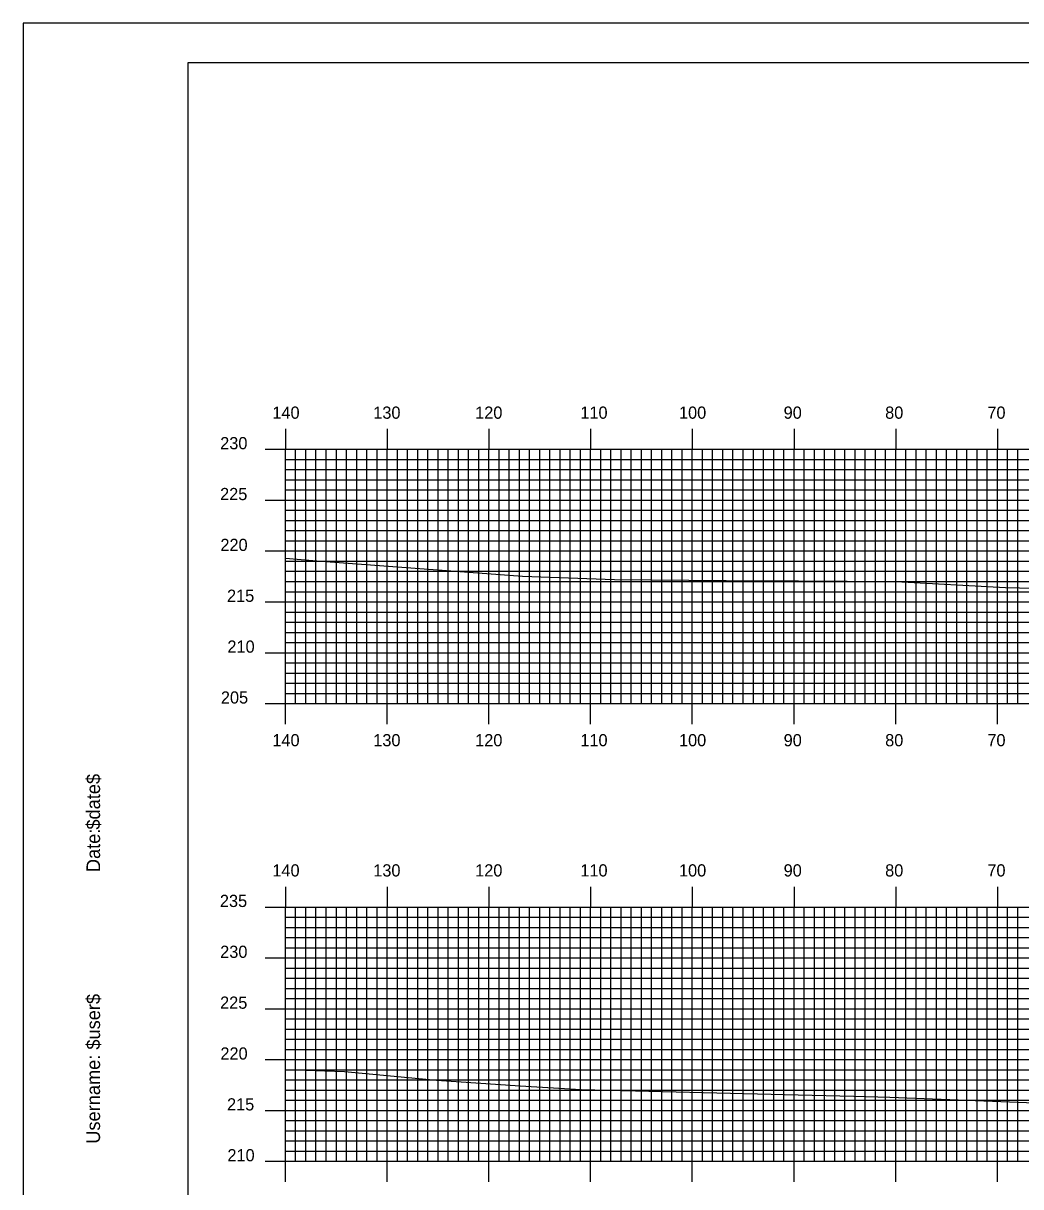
# Model space of a CAD drawing. Extents: x 1819244 to 1819587, y 442591 to 442811.
# Drawn here: x 1819243.9 to 1819342, y 442696.2 to 442810.5 of the extents above; entities that cross this region are included whole.
import ezdxf

# ---------------------------------------------------------------- set-up
doc = ezdxf.new("R2010")
doc.units = 0
for name, color, linetype in [('BORDER', 7, 'Continuous'), ('H_V ANNOTATION', 7, 'Continuous'), ('MAJOR', 7, 'Continuous'), ('MINOR', 7, 'Continuous'), ('PLOT BOUNDARY', 7, 'Continuous'), ('S_Roadway_Centerline', 7, 'Continuous')]:
    doc.layers.add(name, color=color, linetype=linetype)

msp = doc.modelspace()

# ---------------------------------------------------------------- linework, layer by layer
at = {"layer": 'BORDER'}
msp.add_lwpolyline([(1819260.06, 442596.67), (1819580.06, 442596.67), (1819580.06, 442806.67), (1819260.06, 442806.67)], close=True, dxfattribs=at)
at = {"layer": 'MAJOR'}
for p, q in [((1819269.66, 442770.67), (1819269.66, 442768.67)), ((1819279.66, 442770.67), (1819279.66, 442768.67)), ((1819289.66, 442770.67), (1819289.66, 442768.67)), ((1819299.66, 442770.67), (1819299.66, 442768.67)), ((1819309.66, 442770.67), (1819309.66, 442768.67)), ((1819319.66, 442770.67), (1819319.66, 442768.67)), ((1819329.66, 442770.67), (1819329.66, 442768.67)), ((1819339.66, 442770.67), (1819339.66, 442768.67)), ((1819267.66, 442768.67), (1819269.66, 442768.67)), ((1819269.66, 442768.67), (1819549.66, 442768.67)), ((1819269.66, 442743.67), (1819269.66, 442768.67)), ((1819269.66, 442743.67), (1819269.66, 442768.67)), ((1819269.66, 442768.67), (1819549.66, 442768.67)), ((1819279.66, 442743.67), (1819279.66, 442768.67)), ((1819289.66, 442743.67), (1819289.66, 442768.67)), ((1819299.66, 442743.67), (1819299.66, 442768.67)), ((1819309.66, 442743.67), (1819309.66, 442768.67)), ((1819319.66, 442743.67), (1819319.66, 442768.67)), ((1819329.66, 442743.67), (1819329.66, 442768.67)), ((1819339.66, 442743.67), (1819339.66, 442768.67)), ((1819267.66, 442763.67), (1819269.66, 442763.67)), ((1819269.66, 442763.67), (1819549.66, 442763.67)), ((1819267.66, 442758.67), (1819269.66, 442758.67)), ((1819269.66, 442758.67), (1819549.66, 442758.67)), ((1819267.66, 442753.67), (1819269.66, 442753.67)), ((1819269.66, 442753.67), (1819549.66, 442753.67)), ((1819267.66, 442748.67), (1819269.66, 442748.67)), ((1819269.66, 442748.67), (1819549.66, 442748.67)), ((1819267.66, 442743.67), (1819269.66, 442743.67)), ((1819269.66, 442743.67), (1819549.66, 442743.67)), ((1819269.66, 442743.67), (1819549.66, 442743.67)), ((1819269.66, 442741.66), (1819269.66, 442743.67)), ((1819279.66, 442741.66), (1819279.66, 442743.67)), ((1819289.66, 442741.66), (1819289.66, 442743.67)), ((1819299.66, 442741.66), (1819299.66, 442743.67)), ((1819309.66, 442741.66), (1819309.66, 442743.67)), ((1819319.66, 442741.66), (1819319.66, 442743.67)), ((1819329.66, 442741.66), (1819329.66, 442743.67)), ((1819339.66, 442741.66), (1819339.66, 442743.67)), ((1819269.66, 442725.67), (1819269.66, 442723.67)), ((1819279.66, 442725.67), (1819279.66, 442723.67)), ((1819289.66, 442725.67), (1819289.66, 442723.67)), ((1819299.66, 442725.67), (1819299.66, 442723.67)), ((1819309.66, 442725.67), (1819309.66, 442723.67)), ((1819319.66, 442725.67), (1819319.66, 442723.67)), ((1819329.66, 442725.67), (1819329.66, 442723.67)), ((1819339.66, 442725.67), (1819339.66, 442723.67)), ((1819267.66, 442723.67), (1819269.66, 442723.67)), ((1819269.66, 442723.67), (1819549.66, 442723.67)), ((1819269.66, 442698.67), (1819269.66, 442723.67)), ((1819269.66, 442698.67), (1819269.66, 442723.67)), ((1819269.66, 442723.67), (1819549.66, 442723.67)), ((1819279.66, 442698.67), (1819279.66, 442723.67)), ((1819289.66, 442698.67), (1819289.66, 442723.67)), ((1819299.66, 442698.67), (1819299.66, 442723.67)), ((1819309.66, 442698.67), (1819309.66, 442723.67)), ((1819319.66, 442698.67), (1819319.66, 442723.67)), ((1819329.66, 442698.67), (1819329.66, 442723.67)), ((1819339.66, 442698.67), (1819339.66, 442723.67)), ((1819267.66, 442718.67), (1819269.66, 442718.67)), ((1819269.66, 442718.67), (1819549.66, 442718.67)), ((1819267.66, 442713.67), (1819269.66, 442713.67)), ((1819269.66, 442713.67), (1819549.66, 442713.67)), ((1819267.66, 442708.67), (1819269.66, 442708.67)), ((1819269.66, 442708.67), (1819549.66, 442708.67)), ((1819267.66, 442703.67), (1819269.66, 442703.67)), ((1819269.66, 442703.67), (1819549.66, 442703.67)), ((1819267.66, 442698.67), (1819269.66, 442698.67)), ((1819269.66, 442698.67), (1819549.66, 442698.67)), ((1819269.66, 442698.67), (1819549.66, 442698.67)), ((1819269.66, 442696.66), (1819269.66, 442698.67)), ((1819279.66, 442696.66), (1819279.66, 442698.67)), ((1819289.66, 442696.66), (1819289.66, 442698.67)), ((1819299.66, 442696.66), (1819299.66, 442698.67)), ((1819309.66, 442696.66), (1819309.66, 442698.67)), ((1819319.66, 442696.66), (1819319.66, 442698.67)), ((1819329.66, 442696.66), (1819329.66, 442698.67)), ((1819339.66, 442696.66), (1819339.66, 442698.67))]:
    msp.add_line(p, q, dxfattribs=at)
at = {"layer": 'MINOR'}
for p, q in [((1819269.66, 442767.67), (1819549.66, 442767.67)), ((1819269.66, 442767.67), (1819271.67, 442767.67)), ((1819270.66, 442743.67), (1819270.66, 442768.67)), ((1819271.66, 442743.67), (1819271.66, 442768.67)), ((1819272.66, 442743.67), (1819272.66, 442768.67)), ((1819273.66, 442743.67), (1819273.66, 442768.67)), ((1819274.66, 442743.67), (1819274.66, 442768.67)), ((1819275.66, 442743.67), (1819275.66, 442768.67)), ((1819276.66, 442743.67), (1819276.66, 442768.67)), ((1819277.66, 442743.67), (1819277.66, 442768.67)), ((1819278.66, 442743.67), (1819278.66, 442768.67)), ((1819280.66, 442743.67), (1819280.66, 442768.67)), ((1819281.66, 442743.67), (1819281.66, 442768.67)), ((1819282.66, 442743.67), (1819282.66, 442768.67)), ((1819283.66, 442743.67), (1819283.66, 442768.67)), ((1819284.66, 442743.67), (1819284.66, 442768.67)), ((1819285.66, 442743.67), (1819285.66, 442768.67)), ((1819286.66, 442743.67), (1819286.66, 442768.67)), ((1819287.66, 442743.67), (1819287.66, 442768.67)), ((1819288.66, 442743.67), (1819288.66, 442768.67)), ((1819290.66, 442743.67), (1819290.66, 442768.67)), ((1819291.66, 442743.67), (1819291.66, 442768.67)), ((1819292.66, 442743.67), (1819292.66, 442768.67)), ((1819293.66, 442743.67), (1819293.66, 442768.67)), ((1819294.66, 442743.67), (1819294.66, 442768.67)), ((1819295.66, 442743.67), (1819295.66, 442768.67)), ((1819296.66, 442743.67), (1819296.66, 442768.67)), ((1819297.66, 442743.67), (1819297.66, 442768.67)), ((1819298.66, 442743.67), (1819298.66, 442768.67)), ((1819300.66, 442743.67), (1819300.66, 442768.67)), ((1819301.66, 442743.67), (1819301.66, 442768.67)), ((1819302.66, 442743.67), (1819302.66, 442768.67)), ((1819303.66, 442743.67), (1819303.66, 442768.67)), ((1819304.66, 442743.67), (1819304.66, 442768.67)), ((1819305.66, 442743.67), (1819305.66, 442768.67)), ((1819306.66, 442743.67), (1819306.66, 442768.67)), ((1819307.66, 442743.67), (1819307.66, 442768.67)), ((1819308.66, 442743.67), (1819308.66, 442768.67)), ((1819310.66, 442743.67), (1819310.66, 442768.67)), ((1819311.66, 442743.67), (1819311.66, 442768.67)), ((1819312.66, 442743.67), (1819312.66, 442768.67)), ((1819313.66, 442743.67), (1819313.66, 442768.67)), ((1819314.66, 442743.67), (1819314.66, 442768.67)), ((1819315.66, 442743.67), (1819315.66, 442768.67)), ((1819316.66, 442743.67), (1819316.66, 442768.67)), ((1819317.66, 442743.67), (1819317.66, 442768.67)), ((1819318.66, 442743.67), (1819318.66, 442768.67)), ((1819320.66, 442743.67), (1819320.66, 442768.67)), ((1819321.66, 442743.67), (1819321.66, 442768.67)), ((1819322.66, 442743.67), (1819322.66, 442768.67)), ((1819323.66, 442743.67), (1819323.66, 442768.67)), ((1819324.66, 442743.67), (1819324.66, 442768.67)), ((1819325.66, 442743.67), (1819325.66, 442768.67)), ((1819326.66, 442743.67), (1819326.66, 442768.67)), ((1819327.66, 442743.67), (1819327.66, 442768.67)), ((1819328.66, 442743.67), (1819328.66, 442768.67)), ((1819330.66, 442743.67), (1819330.66, 442768.67)), ((1819331.66, 442743.67), (1819331.66, 442768.67)), ((1819332.66, 442743.67), (1819332.66, 442768.67)), ((1819333.66, 442743.67), (1819333.66, 442768.67)), ((1819334.66, 442743.67), (1819334.66, 442768.67)), ((1819335.66, 442743.67), (1819335.66, 442768.67)), ((1819336.66, 442743.67), (1819336.66, 442768.67)), ((1819337.66, 442743.67), (1819337.66, 442768.67)), ((1819338.66, 442743.67), (1819338.66, 442768.67)), ((1819340.66, 442743.67), (1819340.66, 442768.67)), ((1819341.66, 442743.67), (1819341.66, 442768.67)), ((1819269.66, 442766.67), (1819549.66, 442766.67)), ((1819269.66, 442766.67), (1819271.67, 442766.67)), ((1819269.66, 442765.67), (1819549.66, 442765.67)), ((1819269.66, 442765.67), (1819271.67, 442765.67)), ((1819269.66, 442764.67), (1819549.66, 442764.67)), ((1819269.66, 442764.67), (1819271.67, 442764.67)), ((1819269.66, 442762.67), (1819549.66, 442762.67)), ((1819269.66, 442762.67), (1819271.67, 442762.67)), ((1819269.66, 442761.67), (1819549.66, 442761.67)), ((1819269.66, 442761.67), (1819271.67, 442761.67)), ((1819269.66, 442760.67), (1819549.66, 442760.67)), ((1819269.66, 442760.67), (1819271.67, 442760.67)), ((1819269.66, 442759.67), (1819549.66, 442759.67)), ((1819269.66, 442759.67), (1819271.67, 442759.67)), ((1819269.66, 442757.67), (1819549.66, 442757.67)), ((1819269.66, 442757.67), (1819271.67, 442757.67)), ((1819269.66, 442756.67), (1819549.66, 442756.67)), ((1819269.66, 442756.67), (1819271.67, 442756.67)), ((1819269.66, 442755.67), (1819549.66, 442755.67)), ((1819269.66, 442755.67), (1819271.67, 442755.67)), ((1819269.66, 442754.67), (1819549.66, 442754.67)), ((1819269.66, 442754.67), (1819271.67, 442754.67)), ((1819269.66, 442752.67), (1819549.66, 442752.67)), ((1819269.66, 442752.67), (1819271.67, 442752.67)), ((1819269.66, 442751.67), (1819549.66, 442751.67)), ((1819269.66, 442751.67), (1819271.67, 442751.67)), ((1819269.66, 442750.67), (1819549.66, 442750.67)), ((1819269.66, 442750.67), (1819271.67, 442750.67)), ((1819269.66, 442749.67), (1819549.66, 442749.67)), ((1819269.66, 442749.67), (1819271.67, 442749.67)), ((1819269.66, 442747.67), (1819549.66, 442747.67)), ((1819269.66, 442747.67), (1819271.67, 442747.67)), ((1819269.66, 442746.67), (1819549.66, 442746.67)), ((1819269.66, 442746.67), (1819271.67, 442746.67)), ((1819269.66, 442745.67), (1819549.66, 442745.67)), ((1819269.66, 442745.67), (1819271.67, 442745.67)), ((1819269.66, 442744.67), (1819549.66, 442744.67)), ((1819269.66, 442744.67), (1819271.67, 442744.67)), ((1819270.66, 442698.67), (1819270.66, 442723.67)), ((1819271.66, 442698.67), (1819271.66, 442723.67)), ((1819272.66, 442698.67), (1819272.66, 442723.67)), ((1819273.66, 442698.67), (1819273.66, 442723.67)), ((1819274.66, 442698.67), (1819274.66, 442723.67)), ((1819275.66, 442698.67), (1819275.66, 442723.67)), ((1819276.66, 442698.67), (1819276.66, 442723.67)), ((1819277.66, 442698.67), (1819277.66, 442723.67)), ((1819278.66, 442698.67), (1819278.66, 442723.67)), ((1819280.66, 442698.67), (1819280.66, 442723.67)), ((1819281.66, 442698.67), (1819281.66, 442723.67)), ((1819282.66, 442698.67), (1819282.66, 442723.67)), ((1819283.66, 442698.67), (1819283.66, 442723.67)), ((1819284.66, 442698.67), (1819284.66, 442723.67)), ((1819285.66, 442698.67), (1819285.66, 442723.67)), ((1819286.66, 442698.67), (1819286.66, 442723.67)), ((1819287.66, 442698.67), (1819287.66, 442723.67)), ((1819288.66, 442698.67), (1819288.66, 442723.67)), ((1819290.66, 442698.67), (1819290.66, 442723.67)), ((1819291.66, 442698.67), (1819291.66, 442723.67)), ((1819292.66, 442698.67), (1819292.66, 442723.67)), ((1819293.66, 442698.67), (1819293.66, 442723.67)), ((1819294.66, 442698.67), (1819294.66, 442723.67)), ((1819295.66, 442698.67), (1819295.66, 442723.67)), ((1819296.66, 442698.67), (1819296.66, 442723.67)), ((1819297.66, 442698.67), (1819297.66, 442723.67)), ((1819298.66, 442698.67), (1819298.66, 442723.67)), ((1819300.66, 442698.67), (1819300.66, 442723.67)), ((1819301.66, 442698.67), (1819301.66, 442723.67)), ((1819302.66, 442698.67), (1819302.66, 442723.67)), ((1819303.66, 442698.67), (1819303.66, 442723.67)), ((1819304.66, 442698.67), (1819304.66, 442723.67)), ((1819305.66, 442698.67), (1819305.66, 442723.67)), ((1819306.66, 442698.67), (1819306.66, 442723.67)), ((1819307.66, 442698.67), (1819307.66, 442723.67)), ((1819308.66, 442698.67), (1819308.66, 442723.67)), ((1819310.66, 442698.67), (1819310.66, 442723.67)), ((1819311.66, 442698.67), (1819311.66, 442723.67)), ((1819312.66, 442698.67), (1819312.66, 442723.67)), ((1819313.66, 442698.67), (1819313.66, 442723.67)), ((1819314.66, 442698.67), (1819314.66, 442723.67)), ((1819315.66, 442698.67), (1819315.66, 442723.67)), ((1819316.66, 442698.67), (1819316.66, 442723.67)), ((1819317.66, 442698.67), (1819317.66, 442723.67)), ((1819318.66, 442698.67), (1819318.66, 442723.67)), ((1819320.66, 442698.67), (1819320.66, 442723.67)), ((1819321.66, 442698.67), (1819321.66, 442723.67)), ((1819322.66, 442698.67), (1819322.66, 442723.67)), ((1819323.66, 442698.67), (1819323.66, 442723.67)), ((1819324.66, 442698.67), (1819324.66, 442723.67)), ((1819325.66, 442698.67), (1819325.66, 442723.67)), ((1819326.66, 442698.67), (1819326.66, 442723.67)), ((1819327.66, 442698.67), (1819327.66, 442723.67)), ((1819328.66, 442698.67), (1819328.66, 442723.67)), ((1819330.66, 442698.67), (1819330.66, 442723.67)), ((1819331.66, 442698.67), (1819331.66, 442723.67)), ((1819332.66, 442698.67), (1819332.66, 442723.67)), ((1819333.66, 442698.67), (1819333.66, 442723.67)), ((1819334.66, 442698.67), (1819334.66, 442723.67)), ((1819335.66, 442698.67), (1819335.66, 442723.67)), ((1819336.66, 442698.67), (1819336.66, 442723.67)), ((1819337.66, 442698.67), (1819337.66, 442723.67)), ((1819338.66, 442698.67), (1819338.66, 442723.67)), ((1819340.66, 442698.67), (1819340.66, 442723.67)), ((1819341.66, 442698.67), (1819341.66, 442723.67)), ((1819269.66, 442722.67), (1819549.66, 442722.67)), ((1819269.66, 442722.67), (1819271.67, 442722.67)), ((1819269.66, 442721.67), (1819549.66, 442721.67)), ((1819269.66, 442721.67), (1819271.67, 442721.67)), ((1819269.66, 442720.67), (1819549.66, 442720.67)), ((1819269.66, 442720.67), (1819271.67, 442720.67)), ((1819269.66, 442719.67), (1819549.66, 442719.67)), ((1819269.66, 442719.67), (1819271.67, 442719.67)), ((1819269.66, 442717.67), (1819549.66, 442717.67)), ((1819269.66, 442717.67), (1819271.67, 442717.67)), ((1819269.66, 442716.67), (1819549.66, 442716.67)), ((1819269.66, 442716.67), (1819271.67, 442716.67)), ((1819269.66, 442715.67), (1819549.66, 442715.67)), ((1819269.66, 442715.67), (1819271.67, 442715.67)), ((1819269.66, 442714.67), (1819549.66, 442714.67)), ((1819269.66, 442714.67), (1819271.67, 442714.67)), ((1819269.66, 442712.67), (1819549.66, 442712.67)), ((1819269.66, 442712.67), (1819271.67, 442712.67)), ((1819269.66, 442711.67), (1819549.66, 442711.67)), ((1819269.66, 442711.67), (1819271.67, 442711.67)), ((1819269.66, 442710.67), (1819549.66, 442710.67)), ((1819269.66, 442710.67), (1819271.67, 442710.67)), ((1819269.66, 442709.67), (1819549.66, 442709.67)), ((1819269.66, 442709.67), (1819271.67, 442709.67)), ((1819269.66, 442707.67), (1819549.66, 442707.67)), ((1819269.66, 442707.67), (1819271.67, 442707.67)), ((1819269.66, 442706.67), (1819549.66, 442706.67)), ((1819269.66, 442706.67), (1819271.67, 442706.67)), ((1819269.66, 442705.67), (1819549.66, 442705.67)), ((1819269.66, 442705.67), (1819271.67, 442705.67)), ((1819269.66, 442704.67), (1819549.66, 442704.67)), ((1819269.66, 442704.67), (1819271.67, 442704.67)), ((1819269.66, 442702.67), (1819549.66, 442702.67)), ((1819269.66, 442702.67), (1819271.67, 442702.67)), ((1819269.66, 442701.67), (1819549.66, 442701.67)), ((1819269.66, 442701.67), (1819271.67, 442701.67)), ((1819269.66, 442700.67), (1819549.66, 442700.67)), ((1819269.66, 442700.67), (1819271.67, 442700.67)), ((1819269.66, 442699.67), (1819549.66, 442699.67)), ((1819269.66, 442699.67), (1819271.67, 442699.67))]:
    msp.add_line(p, q, dxfattribs=at)
at = {"layer": 'PLOT BOUNDARY'}
msp.add_lwpolyline([(1819243.88, 442590.55), (1819583.88, 442590.55), (1819583.88, 442810.55), (1819243.88, 442810.55)], close=True, dxfattribs=at)
at = {"layer": 'S_Roadway_Centerline'}
for points in [[(1819269.66, 442757.95), (1819272.75, 442757.7), (1819292.96, 442756.18), (1819302.01, 442755.85), (1819313, 442755.78), (1819320.09, 442755.73), (1819329.66, 442755.68), (1819340.46, 442755.09), (1819358.28, 442754.65), (1819368.64, 442754.44), (1819381.6, 442754.61), (1819381.86, 442754.61), (1819382.41, 442754.59), (1819415.25, 442753.8), (1819428.01, 442753.58), (1819435.78, 442753.54), (1819448.77, 442753.64), (1819449.4, 442753.66), (1819462.47, 442753.96), (1819468.07, 442753.86), (1819486.97, 442753.9)], [(1819269.66, 442707.69), (1819275.47, 442707.5), (1819284.5, 442706.65), (1819292.72, 442706.1), (1819298.73, 442705.74), (1819320.06, 442705.22), (1819325.55, 442705.09), (1819329.09, 442704.99), (1819343.37, 442704.43), (1819352.14, 442704.37), (1819360.66, 442704.26), (1819366.79, 442704.24), (1819377.47, 442704.11), (1819392.99, 442703.89), (1819394.88, 442703.88), (1819406.85, 442704.11), (1819411.99, 442704.54), (1819419.82, 442704.68), (1819427.78, 442704.42), (1819453.03, 442704.68), (1819462.65, 442704.51), (1819470.36, 442704.39), (1819486.24, 442704.12)]]:
    msp.add_lwpolyline(points, dxfattribs=at)

# ---------------------------------------------------------------- texts
at = {"layer": 'BORDER'}
for s, p in [('$date$', (1819251.43, 442731.28)), ('Date:', (1819251.43, 442727.1)), ('$user$', (1819251.43, 442709.65)), ('Username:', (1819251.43, 442700.4))]:
    msp.add_text(s, height=1.339, rotation=90, dxfattribs=at).set_placement(p)
at = {"layer": 'H_V ANNOTATION'}
for s, p in [('140', (1819268.37, 442771.67)), ('130', (1819278.29, 442771.67)), ('120', (1819288.31, 442771.67)), ('110', (1819298.65, 442771.67)), ('100', (1819308.35, 442771.67)), ('90', (1819318.64, 442771.67)), ('80', (1819328.62, 442771.67)), ('70', (1819338.67, 442771.67)), ('230', (1819263.24, 442768.67)), ('225', (1819263.23, 442763.67)), ('220', (1819263.26, 442758.67)), ('215', (1819263.91, 442753.67)), ('210', (1819263.95, 442748.67)), ('205', (1819263.31, 442743.67)), ('140', (1819268.37, 442739.47)), ('130', (1819278.29, 442739.47)), ('120', (1819288.31, 442739.47)), ('110', (1819298.65, 442739.47)), ('100', (1819308.35, 442739.47)), ('90', (1819318.64, 442739.47)), ('80', (1819328.62, 442739.47)), ('70', (1819338.67, 442739.47)), ('140', (1819268.37, 442726.67)), ('130', (1819278.29, 442726.67)), ('120', (1819288.31, 442726.67)), ('110', (1819298.65, 442726.67)), ('100', (1819308.35, 442726.67)), ('90', (1819318.64, 442726.67)), ('80', (1819328.62, 442726.67)), ('70', (1819338.67, 442726.67)), ('235', (1819263.21, 442723.67)), ('230', (1819263.24, 442718.67)), ('225', (1819263.23, 442713.67)), ('220', (1819263.26, 442708.67)), ('215', (1819263.91, 442703.67)), ('210', (1819263.95, 442698.67))]:
    msp.add_text(s, height=1.2, dxfattribs=at).set_placement(p)
at = {"layer": 'MAJOR'}
for p in [(1819269.66, 442743.67), (1819269.66, 442698.67)]:
    msp.add_text('-', height=0.012, dxfattribs=at).set_placement(p)

doc.saveas('drawing.dxf')
